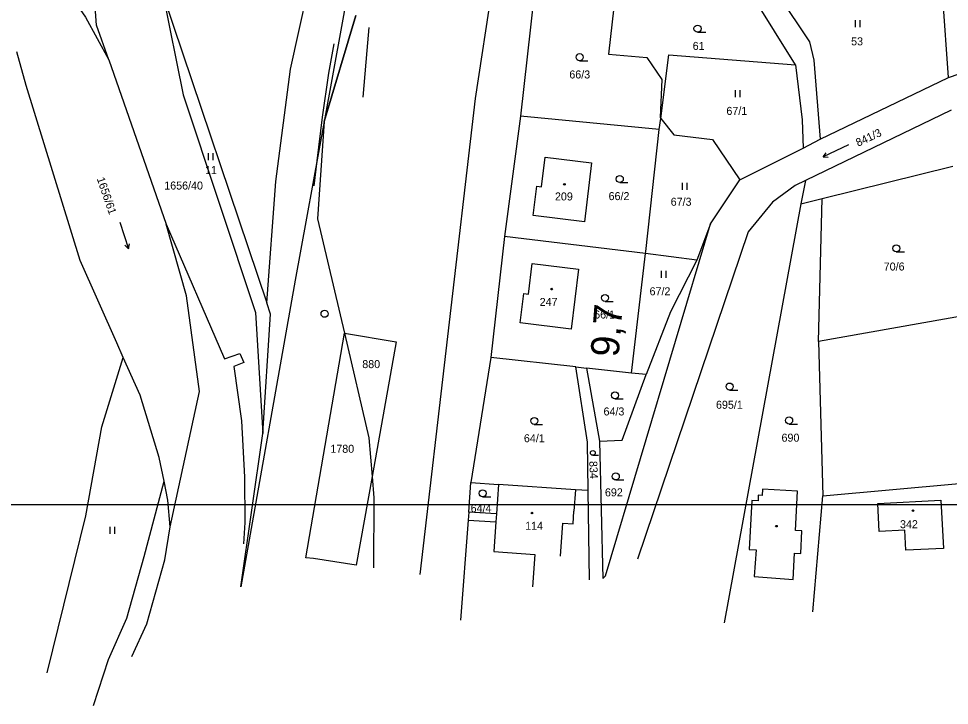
# Model space of a CAD drawing. Extents: x -553916 to -552953, y -1067469 to -1066637.
# Drawn here: x -553675.3 to -553477.6, y -1067452.8 to -1067307 of the extents above; entities that cross this region are included whole.
import ezdxf

# ---------------------------------------------------------------- set-up
doc = ezdxf.new("R2010")
doc.units = 0
for name, color, linetype in [('El2015-Kolej', 7, 'Continuous'), ('Hranice parcel', 7, 'Continuous'), ('Návěst místo trati', 7, 'Continuous'), ('Parcelní čísla', 7, 'Continuous'), ('Vnitřní kresba', 7, 'Continuous'), ('Vrstva 1', 7, 'Continuous'), ('Značky budov', 7, 'Continuous'), ('Značky kultur', 7, 'Continuous')]:
    doc.layers.add(name, color=color, linetype=linetype)

msp = doc.modelspace()

# ---------------------------------------------------------------- linework, layer by layer
at = {"layer": 'El2015-Kolej'}
for points in [[(-553602.15, -1067323.68), (-553601.29, -1067313.74), (-553600.88, -1067308.88)], [(-553612.55, -1067342.51), (-553611.94, -1067337.18), (-553610.81, -1067327.96), (-553609.44, -1067318.59), (-553608.32, -1067312.37)]]:
    msp.add_lwpolyline(points, dxfattribs=at)
at = {"layer": 'Hranice parcel'}
for p, q in [((-553658.81, -1067308.41), (-553660.7, -1067281.64)), ((-553564.68, -1067291.26), (-553568.7, -1067327.71)), ((-553477.8, -1067319.49), (-553479.96, -1067289.49)), ((-553510.29, -1067316.85), (-553521.28, -1067299.18)), ((-553644.72, -1067301.75), (-553622.6, -1067367.36)), ((-553603.7, -1067306.34), (-553610.41, -1067328.83)), ((-553656.17, -1067315.75), (-553658.81, -1067308.41)), ((-553477.8, -1067319.49), (-553452.48, -1067310.66)), ((-553656.17, -1067315.75), (-553643.98, -1067350.66)), ((-553505.07, -1067332.62), (-553477.8, -1067319.49)), ((-553477.28, -1067326.46), (-553508.22, -1067341.4)), ((-553610.41, -1067328.83), (-553611.87, -1067349.52)), ((-553568.7, -1067327.71), (-553572.11, -1067353.26)), ((-553539.25, -1067330.57), (-553568.7, -1067327.71)), ((-553539.25, -1067330.57), (-553538.95, -1067328.2)), ((-553539.08, -1067328.03), (-553538.95, -1067328.2)), ((-553538.95, -1067328.2), (-553536.18, -1067331.71)), ((-553536.18, -1067331.71), (-553527.91, -1067332.68)), ((-553527.91, -1067332.68), (-553522.13, -1067341.26)), ((-553508.66, -1067334.49), (-553505.07, -1067332.62)), ((-553522.13, -1067341.26), (-553508.66, -1067334.49)), ((-553504.63, -1067345.23), (-553476.87, -1067338.35)), ((-553528.38, -1067350.6), (-553522.13, -1067341.26)), ((-553508.22, -1067341.4), (-553509.15, -1067346.35)), ((-553509.15, -1067346.35), (-553525.44, -1067435.26)), ((-553509.15, -1067346.35), (-553504.63, -1067345.23)), ((-553505.45, -1067375.59), (-553504.63, -1067345.23)), ((-553643.98, -1067350.66), (-553631.57, -1067379.26)), ((-553611.87, -1067349.52), (-553606.12, -1067373.77)), ((-553528.38, -1067350.6), (-553531.3, -1067358.3)), ((-553572.11, -1067353.26), (-553575.04, -1067378.95)), ((-553542.19, -1067356.9), (-553572.11, -1067353.26)), ((-553545.17, -1067382.25), (-553542.19, -1067356.9)), ((-553531.3, -1067358.3), (-553542.19, -1067356.9)), ((-553469.3, -1067369.18), (-553505.45, -1067375.59)), ((-553606.12, -1067373.77), (-553600.95, -1067396.02)), ((-553653.09, -1067378.96), (-553654.47, -1067375.83)), ((-553505.45, -1067375.59), (-553504.51, -1067408.36)), ((-553649.54, -1067386.98), (-553653.09, -1067378.96)), ((-553575.04, -1067378.95), (-553579.28, -1067405.5)), ((-553556.95, -1067380.95), (-553575.04, -1067378.95)), ((-553556.95, -1067380.95), (-553554.72, -1067381.2)), ((-553545.17, -1067382.25), (-553554.72, -1067381.2)), ((-553554.72, -1067381.2), (-553551.91, -1067396.75)), ((-553542.03, -1067382.59), (-553545.17, -1067382.25)), ((-553645.48, -1067400.22), (-553649.54, -1067386.98)), ((-553628.1, -1067427.64), (-553623.42, -1067395.12)), ((-553600.95, -1067396.02), (-553600.26, -1067404.19)), ((-553600.95, -1067396.02), (-553600.26, -1067404.19)), ((-553551.91, -1067396.75), (-553551.23, -1067425.89)), ((-553644.44, -1067405.24), (-553645.48, -1067400.22)), ((-553600.26, -1067404.19), (-553603.6, -1067423.08)), ((-553579.71, -1067411.78), (-553579.28, -1067405.5)), ((-553579.28, -1067405.5), (-553573.4, -1067405.9)), ((-553504.51, -1067408.36), (-553475.58, -1067405.74)), ((-553554.04, -1067426.13), (-553554.35, -1067407.2)), ((-553506.64, -1067432.96), (-553504.51, -1067408.36)), ((-553579.71, -1067411.78), (-553579.83, -1067413.47)), ((-553579.83, -1067413.47), (-553581.5, -1067434.75))]:
    msp.add_line(p, q, dxfattribs=at)
for points in [[(-553590.02, -1067425.05), (-553578.3, -1067323.96), (-553571.08, -1067276.6), (-553571.65, -1067255.09), (-553574.19, -1067242.71)], [(-553679.12, -1067280.91), (-553661.1, -1067306.72), (-553656.17, -1067315.75)], [(-553520.36, -1067292.41), (-553507.33, -1067311.94), (-553506.4, -1067315.83), (-553505.07, -1067332.62)], [(-553644.72, -1067301.75), (-553640.4, -1067323.22), (-553625.01, -1067369.42), (-553623.42, -1067395.12)], [(-553548.89, -1067304.57), (-553550.06, -1067314.58), (-553541.86, -1067315.26), (-553538.68, -1067319.9), (-553539.08, -1067328.03)], [(-553654.47, -1067375.83), (-553662.26, -1067358.39), (-553673.71, -1067321.24), (-553675.68, -1067314.09)], [(-553538.95, -1067328.2), (-553537.23, -1067314.72), (-553510.29, -1067316.85)], [(-553510.29, -1067316.85), (-553508.9, -1067328.46), (-553508.66, -1067334.49)], [(-553542.19, -1067356.9), (-553542.12, -1067356.43), (-553539.25, -1067330.57)], [(-553563.51, -1067336.41), (-553553.63, -1067337.6), (-553555.15, -1067350.16), (-553566.02, -1067348.84), (-553565.27, -1067342.59), (-553564.27, -1067342.71), (-553563.51, -1067336.41)], [(-553508.22, -1067341.4), (-553510.38, -1067342.44), (-553515.22, -1067345.99), (-553520.38, -1067352.25), (-553543.87, -1067421.79)], [(-553643.17, -1067414.9), (-553636.88, -1067386.17), (-553639.67, -1067365.88), (-553643.98, -1067350.66)], [(-553551.23, -1067425.89), (-553550.67, -1067425.31), (-553528.38, -1067350.6)], [(-553531.3, -1067358.3), (-553536.84, -1067369.26), (-553542.03, -1067382.59)], [(-553567.04, -1067365.48), (-553566.24, -1067358.98), (-553556.41, -1067360.17), (-553557.95, -1067372.93), (-553568.79, -1067371.62), (-553568.04, -1067365.36), (-553567.04, -1067365.48)], [(-553623.42, -1067395.12), (-553621.8, -1067369.77), (-553622.6, -1067367.36)], [(-553606.12, -1067373.77), (-553595.12, -1067375.65), (-553600.26, -1067404.19)], [(-553631.57, -1067379.26), (-553628.31, -1067378.1), (-553627.5, -1067380.01), (-553629.62, -1067380.89), (-553627.95, -1067392.42), (-553627.34, -1067404.34), (-553627.3, -1067414.01), (-553627.58, -1067418.54)], [(-553669.27, -1067445.9), (-553661.03, -1067412.6), (-553657.63, -1067393.68), (-553653.09, -1067378.96)], [(-553554.35, -1067407.2), (-553554.52, -1067396.92), (-553556.95, -1067380.95)], [(-553551.91, -1067396.75), (-553547.15, -1067396.49), (-553542.03, -1067382.59)], [(-553659.4, -1067452.82), (-553656.26, -1067443.05), (-553652.34, -1067434.28), (-553648.64, -1067421.21), (-553644.44, -1067405.24)], [(-553643.17, -1067414.9), (-553643.61, -1067409.25), (-553644.44, -1067405.24)], [(-553600.26, -1067404.19), (-553599.87, -1067408.74), (-553599.97, -1067423.61)], [(-553600.26, -1067404.19), (-553599.87, -1067408.74), (-553599.97, -1067423.61)], [(-553573.4, -1067405.9), (-553573.83, -1067412.18), (-553579.71, -1067411.78)], [(-553554.35, -1067407.2), (-553557.04, -1067407.02), (-553573.4, -1067405.9)], [(-553520.12, -1067419.71), (-553518.67, -1067419.79), (-553519.07, -1067425.49), (-553510.8, -1067426.07), (-553510.52, -1067420.48), (-553509.17, -1067420.55), (-553508.94, -1067415.79), (-553510.29, -1067415.72), (-553509.86, -1067407.33), (-553517.34, -1067406.94), (-553517.41, -1067408.24), (-553518.21, -1067408.2), (-553518.27, -1067409.37), (-553519.57, -1067409.3), (-553520.12, -1067419.71)], [(-553487.11, -1067415.6), (-553492.55, -1067415.89), (-553492.85, -1067409.99), (-553479.42, -1067409.27), (-553478.87, -1067419.49), (-553486.87, -1067419.9), (-553487.11, -1067415.6)], [(-553579.83, -1067413.47), (-553573.95, -1067413.88), (-553574.38, -1067420.16), (-553565.7, -1067420.76), (-553566.17, -1067427.63)], [(-553651.28, -1067442.47), (-553648.07, -1067435.48), (-553644.26, -1067421.89), (-553643.17, -1067414.9)]]:
    msp.add_lwpolyline(points, dxfattribs=at)
at = {"layer": 'Návěst místo trati'}
msp.add_circle((-553610.34, -1067369.67), 0.75, dxfattribs=at)
at = {"layer": 'Vnitřní kresba'}
for p, q in [((-553557.04, -1067407.02), (-553557.36, -1067411.61)), ((-553557.54, -1067414.3), (-553557.36, -1067411.61)), ((-553573.83, -1067412.18), (-553573.95, -1067413.88)), ((-553560.22, -1067421.14), (-553559.74, -1067414.15)), ((-553559.74, -1067414.15), (-553557.54, -1067414.3))]:
    msp.add_line(p, q, dxfattribs=at)
at = {"layer": 'Vrstva 1'}
for p, q in [((-553610.41, -1067328.83), (-553603.7, -1067306.34)), ((-553610.41, -1067328.83), (-553611.87, -1067349.52)), ((-553622.6, -1067367.36), (-553620.69, -1067341.58)), ((-553611.87, -1067349.52), (-553606.12, -1067373.77)), ((-553606.12, -1067373.77), (-553600.95, -1067396.02)), ((-552953.11, -1067410.27), (-553794.11, -1067410.27))]:
    msp.add_line(p, q, dxfattribs=at)
for points in [[(-553576.73, -1067221.16), (-553579.9, -1067226.28), (-553584.2, -1067237.72), (-553592.61, -1067257.79), (-553598.74, -1067274.59), (-553603.72, -1067298.29), (-553604.8, -1067298.11), (-553610.41, -1067328.83)], [(-553620.69, -1067341.58), (-553617.56, -1067317.76), (-553612.15, -1067293.03), (-553604.5, -1067271.72), (-553593.43, -1067246.52), (-553584.77, -1067229.49)], [(-553610.41, -1067328.83), (-553616.57, -1067362.55), (-553628.1, -1067427.64)], [(-553603.6, -1067423.08), (-553612.7, -1067421.66), (-553614.31, -1067421.48), (-553606.12, -1067373.77)]]:
    msp.add_lwpolyline(points, dxfattribs=at)
at = {"layer": 'Značky budov'}
for centre in [(-553559.39, -1067342.19), (-553562.1, -1067364.44), (-553566.29, -1067411.99), (-553485.36, -1067411.47), (-553514.35, -1067414.77)]:
    msp.add_circle(centre, 0.175, dxfattribs=at)
at = {"layer": 'Značky kultur'}
for p, q in [((-553497.58, -1067308.83), (-553497.58, -1067307.33)), ((-553496.58, -1067308.83), (-553496.58, -1067307.33)), ((-553531.12, -1067309.88), (-553529.37, -1067309.88)), ((-553556.16, -1067315.94), (-553554.41, -1067315.94)), ((-553523.06, -1067323.69), (-553523.06, -1067322.19)), ((-553522.06, -1067323.69), (-553522.06, -1067322.19)), ((-553499.02, -1067333.81), (-553504.46, -1067336.35)), ((-553635, -1067337.06), (-553635, -1067335.56)), ((-553634, -1067337.06), (-553634, -1067335.56)), ((-553504.46, -1067336.35), (-553503.78, -1067335.48)), ((-553504.46, -1067336.35), (-553503.36, -1067336.39)), ((-553547.64, -1067341.81), (-553545.89, -1067341.81)), ((-553534.33, -1067343.34), (-553534.33, -1067341.84)), ((-553533.33, -1067343.34), (-553533.33, -1067341.84)), ((-553653.82, -1067350.2), (-553651.97, -1067355.9)), ((-553651.97, -1067355.9), (-553652.74, -1067355.13)), ((-553651.97, -1067355.9), (-553651.79, -1067354.82)), ((-553488.91, -1067356.53), (-553487.16, -1067356.53)), ((-553538.77, -1067362.05), (-553538.77, -1067360.55)), ((-553537.77, -1067362.05), (-553537.77, -1067360.55)), ((-553550.77, -1067367.06), (-553549.02, -1067367.06)), ((-553524.31, -1067385.88), (-553522.56, -1067385.88)), ((-553548.65, -1067387.74), (-553546.9, -1067387.74)), ((-553565.79, -1067393.18), (-553564.04, -1067393.18)), ((-553511.67, -1067393.08), (-553509.92, -1067393.08)), ((-553553.35, -1067399.71), (-553552.18, -1067399.71)), ((-553548.49, -1067404.96), (-553546.74, -1067404.96)), ((-553576.77, -1067408.54), (-553575.02, -1067408.54)), ((-553655.91, -1067416.38), (-553655.91, -1067414.88)), ((-553654.91, -1067416.38), (-553654.91, -1067414.88))]:
    msp.add_line(p, q, dxfattribs=at)
for centre, radius in [((-553531.12, -1067309.13), 0.75), ((-553556.16, -1067315.19), 0.75), ((-553547.64, -1067341.06), 0.75), ((-553488.91, -1067355.78), 0.75), ((-553550.77, -1067366.31), 0.75), ((-553548.65, -1067386.99), 0.75), ((-553524.31, -1067385.13), 0.75), ((-553565.79, -1067392.43), 0.75), ((-553511.67, -1067392.33), 0.75), ((-553553.36, -1067399.21), 0.502), ((-553548.49, -1067404.21), 0.75), ((-553576.77, -1067407.79), 0.75)]:
    msp.add_circle(centre, radius, dxfattribs=at)

# ---------------------------------------------------------------- texts
at = {"layer": 'Návěst místo trati'}
msp.add_text('9,7', height=6, rotation=85.4407, dxfattribs=at).set_placement((-553547.89, -1067379.01))
at = {"layer": 'Parcelní čísla'}
for s, p in [('53', (-553498.5, -1067312.68)), ('61', (-553532.15, -1067313.65)), ('66/3', (-553558.35, -1067319.71)), ('67/1', (-553524.99, -1067327.45)), ('11', (-553635.73, -1067340.01)), ('1656/40', (-553644.39, -1067343.3)), ('209', (-553561.4, -1067345.61)), ('66/2', (-553550.01, -1067345.54)), ('67/3', (-553536.82, -1067346.74)), ('70/6', (-553491.57, -1067360.49)), ('67/2', (-553541.31, -1067365.75)), ('247', (-553564.65, -1067368.01)), ('66/1', (-553553.07, -1067370.68)), ('880', (-553602.33, -1067381.21)), ('695/1', (-553527.2, -1067389.84)), ('64/3', (-553551.09, -1067391.26)), ('64/1', (-553568, -1067396.95)), ('690', (-553513.28, -1067396.83)), ('692', (-553550.79, -1067408.44)), ('64/4', (-553579.31, -1067411.82)), ('114', (-553567.73, -1067415.54)), ('342', (-553488.11, -1067415.2))]:
    msp.add_text(s, height=1.7, dxfattribs=at).set_placement(p)
for s, rotation, p in [('841/3', 25, (-553497.02, -1067334.22)), ('1656/61', 289, (-553658.75, -1067340.99)), ('834', 273, (-553554.13, -1067400.97))]:
    msp.add_text(s, height=1.7, rotation=rotation, dxfattribs=at).set_placement(p)
at = {"layer": 'Vrstva 1'}
msp.add_text('1780', height=1.7, dxfattribs=at).set_placement((-553609.11, -1067399.19))

doc.saveas('drawing.dxf')
